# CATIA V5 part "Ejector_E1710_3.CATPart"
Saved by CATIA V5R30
Part number: Vyhazovac_2.5x160_1
Nomenclature: E1710/2.5x160
Description: MEUSBURGER
Property "Material": "1.221"
Publications: "__DrillHole", "Base"
Bounding box of the stored display mesh (mm): x -2.499 to 2.499, y -2.499 to 2.499, z 0 to 152
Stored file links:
  E:\Bakalarka\Model\Forma_v7\Ejector_E1710_3.CATPart
  E:\dev\MoldDesign\intel_a\startup\components\MoldCatalog\Ejector\Meusburger\Ejector_E1710\TableE1710.txt
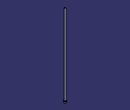
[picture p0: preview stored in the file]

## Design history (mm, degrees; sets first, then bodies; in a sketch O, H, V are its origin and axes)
Parameters
  Ref = "E1710/2.5x160" {design table}
  D1 = 2.5 mm {design table}
  D3 = 5 mm {design table}
  L = 160 mm {design table}
  L3 = 2 mm {design table}
  R = 0.3 mm {design table}
  k_d3 = 6 mm {design table}
  k_d1 = 2.7 mm {design table}
  k_F = 0.3 mm {design table}
  kl = 17 mm {design table}
  Mat = "1.221" {design table}
  HeatTreat = "ISO6751" {design table}
  Offset_Parting = 10 mm
  Anti_Rotation = "Normal"
  Anti_Rotation_D = 1.55 mm
  Anti_Rotation_D_Icut = 1.55 mm
  Add_Length_L = 0.0877 mm
  Add_Length_D3 = 0 mm
  SupplierRef = "Meusburger 2017"
  BmpRef = "F_MldEjectorD1"
  DrillHole_Length = 225 mm
  ValidationTest = false
  Anti_Rotation_D_min = 1.55 mm {= OffSet_D1 /2}
  Anti_Rotation_D_max = 2.425 mm {= D3/2-0.075mm}
  Anti_Rotation_D_ref = 1.55 mm {= Anti_Rotation_D}
  Anti_Rotation_D_Icut_ref = 1.55 mm {= Anti_Rotation_D_Icut}
  Anti_Rotation_Ref_Icut = 2.3246 mm
  Offset_L = 20 mm
  D = 2.5 mm {= D1}
  OffSet_D1 = 3.1 mm {= D1+2*R}
  OffSet_D3 = 6 mm {= D3+1mm}
  XG_Split = -47 mm
  YG_Split = 53.5 mm
  ZG_Split = -198 mm
  DirX_Split = 0 mm
  DirY_Split = 0 mm
  DirZ_Split = 1 mm
Set1 "BaseBody"
  Point1 "Base": (0, 0, 0)
  Plane1: type Offset, RefPlane xy-plane, Offset 225 {= DrillHole_Length}, reversed
  Sketch1 "Sketch.2" on xy-plane, origin (0, 0, 0), H (1, 0, 0), V (0, 1, 0)
    point P1 (-0.46, 1.1623)
    point P2 (0.46, 1.1623)
    construction line L1 (-0.46, 1.1623) -> (0.46, 1.1623)
    point P3 (0.46, -1.1623)
    line L2 (0.46, -1.1623) -> (0.46, 1.1623)
    point P4 (-0.46, -1.1623)
    construction line L3 (0.46, -1.1623) -> (-0.46, -1.1623)
    line L4 (-0.46, 1.1623) -> (-0.46, -1.1623)
    point P5 (-0.21, 1.1623)
    arc A1 centre (-0.21, 1.1623) radius 0.25 from (-0.21, 1.4123) to (-0.46, 1.1623) ccw
    point P7 (0.21, 1.1623)
    point P8 (0.21, 1.4123)
    arc A2 centre (0.21, 1.1623) radius 0.25 from (0.46, 1.1623) to (0.21, 1.4123) ccw
    line L5 (-0.21, 1.4123) -> (0.21, 1.4123)
    point P9 (-0.46, -1.1623)
    arc A3 centre (-0.21, -1.1623) radius 0.25 from (-0.46, -1.1623) to (-0.21, -1.4123) ccw
    point P11 (0.21, -1.4123)
    line L6 (-0.21, -1.4123) -> (0.21, -1.4123)
    point P12 (0.46, -1.1623)
    arc A4 centre (0.21, -1.1623) radius 0.25 from (0.21, -1.4123) to (0.46, -1.1623) ccw
    point P14 (-0.46, 1.1623)
    point P15 (-0.46, -1.1623)
    point P16 (0.46, 1.1623)
    point P17 (0.46, -1.1623)
    reference projected circle E1 centre (0, 0) radius 1.25 from edge [face of Shaft1 from Sketch2.L3 | face of Shaft1 from Sketch2.L4]
    reference projected circle E2 centre (0, 0) radius 1.25 from edge [face of Shaft1 from Sketch2.L3 | face of Shaft1 from Sketch2.L4]
    reference projected circle E3 centre (0, 0) radius 1.25 from edge [face of Shaft1 from Sketch2.L3 | face of Shaft1 from Sketch2.L4]
    reference projected circle E4 centre (0, 0) radius 1.25 from edge [face of Shaft1 from Sketch2.L3 | face of Shaft1 from Sketch2.L4]
    point P18 (-0.46, -1.1623)
    point P19 (-0.21, -1.4123)
    point P20 (0.21, -1.4123)
    point P21 (0.46, -1.1623)
    point P22 (-0.21, -1.4123)
    point P23 (0.21, -1.4123)
    distance P14 P15 = 2.3246 (reference)
    distance P16 P17 = 2.3246 (reference)
    distance L1 P14 = 0 (reference)
    radius A1 = 1.25
    distance L4 V = 1.56
    distance L2 V = 2.435
    distance L5 L6 = 5
    horizontal: L1 H, L3 H, L5 H
    vertical: L2 V, L4 V
    coincidence: P5 L1, P7 L1, P3 P12, P14 L4, P15 L4, P16 L2, P17 L2, P14 E1, P15 E2, P16 E3, P17 E4, P3 P21, P4 P18, P20 P23, P19 P22
    tangency: A1 L4, A2 L2, A2 L5, A1 L5
    symmetry: P1 P9 H, A1 A3 H, P8 P11 H, L5 L6 H, P2 P12 H, A2 A4 H
  DatumSurface1
Body1 "PartBody" (main body)
  Sketch2 "Sketch.1" on zx-plane, origin (0, 0, 0), H (-1, 0, 0), V (0, 0, 1)
    point P1 (0, 160)
    line L1 (1.25, 160) -> (0, 160)
    line L2 (1.25, 2) -> (1.25, 160)
    line L3 (2.5, 2) -> (1.25, 2)
    line L4 (2.5, 0) -> (2.5, 2)
    point P5 (0, 0)
    line L5 (0, 0) -> (2.5, 0)
    point P6 (0, 160)
    axis line L6 (0, 160) -> (0, 0)
    point P7 (0, 0)
    point P8 (1.25, 2)
    point P9 (1.25, 2)
    line L7 (0, 160) -> (0, 0)
    distance L5 L3 = 2 {= L3}
    distance L5 L1 = 160 {= L}
    distance L2 L6 = 1.25 {= D1 /2}
    distance L4 L6 = 2.5 {= D3 /2}
    coincidence: L6 P5, P1 L6, L5 H, L6 V, P7 O, P6 P1, P8 P9
    vertical: L2 V, L7 V
    horizontal: L1 H
  Shaft1 "Shaft.1": profile Sketch2, axis Sketch2.L6, angle 360
  Pocket1 "Pocket.1": profile Sketch1, direction (0, 0, 1), length 3, outer side, deactivated
  Pocket2 "Pocket.2": profile Sketch1, direction (0, 0, 1), length 3, outer side, deactivated
  Fillet1: radius 0.3 {= R}, on edge [face of Shaft1 from Sketch2.L2 | face of Shaft1 from Sketch2.L3]
  Pocket3: profile face of Shaft1 from Sketch2.L1, direction along face of Shaft1 from Sketch2.L1 reversed, up to face of DatumSurface1
Body2 "__DrillHole"
  Sketch3 "Sketch.3" on face of Shaft1, origin (0, 0, 0), H (1, 0, 0), V (0, -1, 0)
    point P1 (0, 0)
    reference projected point E1 (0, 0) from Point1
    coincidence: E1 P1
  Hole1 "Hole.1": placed by Sketch3, at (0, 0, 0) direction (0, 0, 1), diameter 3.1 {= OffSet_D1}, depth 140 {= L-Offset_L}
  Sketch4 "Sketch.4" on face of Shaft1, origin (0, 0, 0), H (1, 0, 0), V (0, -1, 0)
    point P1 (0, 0)
    reference projected point E1 (0, 0) from Point1
    coincidence: E1 P1
  Hole2 "Hole.2": placed by Sketch4, at (0, 0, 0) direction (0, 0, 1), diameter 2.5 {= D1}, depth 160 {= L}
  Sketch5 "Sketch.5" on face of Shaft1 from Sketch2.L3, origin (0, 0, 2), H (1, 0, 0), V (0, 1, 0)
    point P1 (0, 0)
    reference projected point E1 (0, 0) from Point1
    coincidence: E1 P1
  Hole3 "Hole.3": placed by Sketch5, at (0, 0, 2) direction (0, 0, -1), diameter 6 {= OffSet_D3}, depth 227 {= L3 +DrillHole_Length}
  Chamfer1: length 0.3 {= k_F}, angle 45, on edge [face of Hole1 | face of Hole3]
  Body3 "__Body.1"
    Pocket4 "Pocket.3": profile Sketch1, direction (0, 0, -1), length 225, opposite side length 2, deactivated
  Assemble1: tool Body3
  Chamfer2: length 0.3 {= k_F}, angle 45, on edge [start face of Pocket4 | face of Hole1], deactivated
  Body4 "__Body.2"
    Pocket5 "Pocket.4": profile Sketch1, direction (0, 0, -1), length 225, opposite side length 2, deactivated
  Assemble2: tool Body4
  Chamfer3: length 0.3 {= k_F}, angle 45, on edge [start face of Pocket5 | face of Hole1], deactivated
Relations
  design table "TableE1710", configuration 134, drives Ref, D1, D3, L, L3, R, k_d3, k_d1, k_F, kl, Mat, HeatTreat
  Offset_L = 20mm (deactivated)
  rule "Cut_Head_rule":
    let sketch_cut (length)
    let PartBody_Pocket_Sketch (Boolean)
    let I_PartBody_Pocket (Boolean)
    let D_PartBody_Pocket (Boolean)
    let N_DrillHole_Hole (Boolean)
    let N_DrillHole_Hole_Sketch (Boolean)
    let I_DrillHole_Pocket (Boolean)
    let D_DrillHole_Pocket (Boolean)
    /* --------------------------------------------------------------------------------------*/
    if Anti_Rotation =="Normal"
    {
    	sketch_cut=Anti_Rotation_D_max
    	PartBody_Pocket_Sketch = false
    	I_PartBody_Pocket = false
    	D_PartBody_Pocket = false
    	N_DrillHole_Hole = true
    	N_DrillHole_Hole_Sketch = true
    	I_DrillHole_Pocket = false
    	D_DrillHole_Pocket = false
    	Chamfer1.Activity= true
    	Chamfer2.Activity= false
    	Chamfer3.Activity= false
    }
    if Anti_Rotation == "I_Cut"
    {
    	sketch_cut=Anti_Rotation_D_Icut_ref
    	PartBody_Pocket_Sketch = true
    	I_PartBody_Pocket = true
    	D_PartBody_Pocket = false
    	N_DrillHole_Hole = false
    	N_DrillHole_Hole_Sketch = false
    	I_DrillHole_Pocket = true
    	D_DrillHole_Pocket = false
    	Chamfer1.Activity= false
    	Chamfer2.Activity= true
    	Chamfer3.Activity= false
    }
    if Anti_Rotation =="D_Cut"
    {
    	sketch_cut=Anti_Rotation_D_max
    	PartBody_Pocket_Sketch = true
    	I_PartBody_Pocket = false
    	D_PartBody_Pocket = true
    	N_DrillHole_Hole = false
    	N_DrillHole_Hole_Sketch = false
    	I_DrillHole_Pocket = false
    	D_DrillHole_Pocket = true
    	Chamfer1.Activity= false
    	Chamfer2.Activity= false
    	Chamfer3.Activity= true
    }
    /* --------------------------------------------------------------------------------------*/
    Sketch1.distance(L2 V) = sketch_cut+0.01mm
    Sketch1.distance(L4 V) =Anti_Rotation_D_ref+0.01mm
    Sketch1.radius(A1) =D/2
    Pocket4.FirstLimit.Depth = DrillHole_Length
    Pocket5.FirstLimit.Depth = DrillHole_Length
    Pocket1.FirstLimit.Depth = L3+1mm
    Pocket2.FirstLimit.Depth = L3+1mm
    Pocket4.SecondLimit.Depth = L3
    Pocket5.SecondLimit.Depth =L3
    Pocket1.Activity = I_PartBody_Pocket
    Pocket2.Activity = D_PartBody_Pocket
    Sketch1.Activity =PartBody_Pocket_Sketch
    Hole3.Activity= N_DrillHole_Hole
    Sketch5.Activity = N_DrillHole_Hole_Sketch
    Pocket4.Activity = I_DrillHole_Pocket
    Pocket5.Activity  = D_DrillHole_Pocket
  rule "Anti_Rotation_Icut_constrain":
    let Ref1(length)
    let Ref2(length)
    let Ref3(length)
    let Diam1(length)
    let Diam2(length)
    let Add_Length_Lmin (length)
    Ref1=Sketch1.distance(P14 P15)
    Ref2=Sketch1.distance(P16 P17)
    Diam1=D
    Diam2=D3
    /* --------------------------------------------------------------------*/
    if Ref1 >Ref2
    	Anti_Rotation_Ref_Icut = Ref1
    else
    	Anti_Rotation_Ref_Icut  =Ref2
    Add_Length_D3 .InferiorRange=Anti_Rotation_Ref_Icut /2+Diam1/2 -Diam2/2
    if Add_Length_D3 .InferiorRange<0mm
    	Add_Length_D3 .InferiorRange=0mm
    if ValidationTest == "true"
    	Ref3   = 2*Add_Length_L +Anti_Rotation_Ref_Icut  +2*Diam1/2
    else
    	Ref3  =Diam2+2*Add_Length_D3
    if Ref3 <Diam2
    {
    	Ref3 =Diam2
    }
    /* --------------------------------------------------------------------*/
    Sketch1.distance(L5 L6) = Ref3
    Add_Length_L .InferiorRange=Diam2/2-Anti_Rotation_Ref_Icut/2-Diam1/2
    Add_Length_Lmin=Diam2/2-Anti_Rotation_Ref_Icut/2-Diam1/2
    if Add_Length_Lmin<0mm
    	Add_Length_L .InferiorRange=0mm
    else
    	Add_Length_L .InferiorRange=Add_Length_Lmin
